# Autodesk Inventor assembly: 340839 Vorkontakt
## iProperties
Created: 2006-04
Part Number: 340839 Vorkontakt
Document SubType Name: Assembly
Designer: I.Baliuc
Description: Vorkontakt
Cost Center: 23,354 kg
Authority: 4948814 mm^3
Stock Number: 340839 Vorkontakt
Mass: 24161.9 g
Surface Area: 23527.2 cm^2
Volume: 4983.35 cm^3
Density: 4.84852 g/cm^3
Title: Vorkontakt, HSLT
Company: Mayer & Müller AG
Zweck: HSLT
SaveDate: 2006-11-03
SaveTime: 02:40
TotalMass: 23,354 kg
TotalVolume: 4948814 mm^3
Author: T.Messerschmitt
Revision Number: 340839
